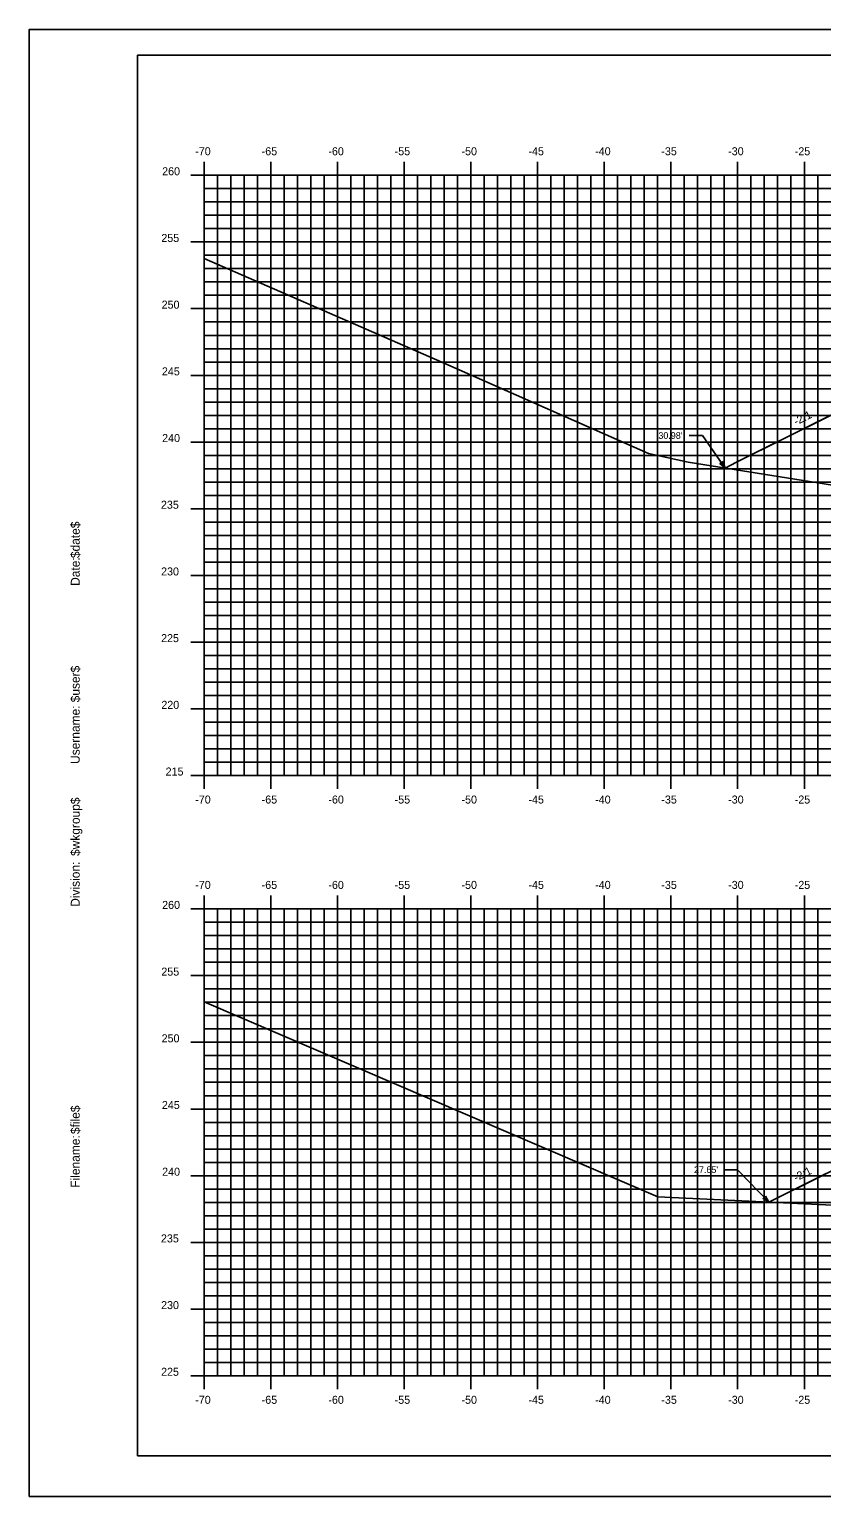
# Model space of a CAD drawing. Extents: x 1160718 to 1173142, y 616002 to 617630.
# Drawn here: x 1169657.5 to 1169716.9, y 616613.9 to 616723.9 of the extents above; entities that cross this region are included whole.
import ezdxf

# ---------------------------------------------------------------- set-up
doc = ezdxf.new("R2010")
doc.units = 0
for name, color, linetype in [('ANNOTATION', 7, 'Continuous'), ('BORDER', 7, 'Continuous'), ('D_Roadway_Centerline', 7, 'Continuous'), ('D_Roadway_SlopeLines', 7, 'Continuous'), ('H_V ANNOTATION', 7, 'Continuous'), ('MAJOR', 7, 'Continuous'), ('MINOR', 7, 'Continuous'), ('PLOT BOUNDARY', 7, 'Continuous'), ('S_Roadway_Centerline', 7, 'Continuous')]:
    doc.layers.add(name, color=color, linetype=linetype)

msp = doc.modelspace()

# ---------------------------------------------------------------- linework, layer by layer
at = {"layer": 'ANNOTATION'}
for p, q in [((1169707, 616693.42), (1169708, 616693.42)), ((1169709.7, 616690.98), (1169708, 616693.42)), ((1169709.64, 616638.38), (1169710.64, 616638.38)), ((1169712.99, 616635.94), (1169710.64, 616638.38))]:
    msp.add_line(p, q, dxfattribs=at)
for points in [[(1169709.52, 616691.46), (1169709.7, 616690.98), (1169709.31, 616691.32)], [(1169712.73, 616636.39), (1169712.99, 616635.94), (1169712.55, 616636.22)]]:
    msp.add_lwpolyline(points, close=True, dxfattribs=at)
at = {"layer": 'BORDER'}
for p, q in [((1169825.64, 616721.93), (1169665.64, 616721.93)), ((1169665.64, 616721.93), (1169665.64, 616616.93)), ((1169665.64, 616616.93), (1169825.64, 616616.93))]:
    msp.add_line(p, q, dxfattribs=at)
at = {"layer": 'D_Roadway_Centerline'}
msp.add_line((1169712.99, 616635.94), (1169717.24, 616638.07), dxfattribs=at)
msp.add_lwpolyline([(1169709.7, 616690.98), (1169710.55, 616691.41), (1169717.65, 616694.95), (1169721.64, 616696.95), (1169724.64, 616697.01), (1169740.64, 616696.37), (1169756.64, 616695.73)], dxfattribs=at)
at = {"layer": 'D_Roadway_SlopeLines'}
for points in [[(1169721.64, 616696.95), (1169710.55, 616691.41)], [(1169710.55, 616691.41), (1169709.7, 616690.98)], [(1169721.64, 616640.27), (1169712.99, 616635.94)]]:
    msp.add_lwpolyline(points, dxfattribs=at)
at = {"layer": 'MAJOR'}
for p, q in [((1169670.64, 616713.93), (1169670.64, 616712.93)), ((1169675.64, 616713.93), (1169675.64, 616712.93)), ((1169680.64, 616713.93), (1169680.64, 616712.93)), ((1169685.64, 616713.93), (1169685.64, 616712.93)), ((1169690.64, 616713.93), (1169690.64, 616712.93)), ((1169695.64, 616713.93), (1169695.64, 616712.93)), ((1169700.64, 616713.93), (1169700.64, 616712.93)), ((1169705.64, 616713.93), (1169705.64, 616712.93)), ((1169710.64, 616713.93), (1169710.64, 616712.93)), ((1169715.64, 616713.93), (1169715.64, 616712.93)), ((1169669.64, 616712.93), (1169670.64, 616712.93)), ((1169670.64, 616712.93), (1169810.64, 616712.93)), ((1169670.64, 616667.93), (1169670.64, 616712.93)), ((1169670.64, 616667.93), (1169670.64, 616712.93)), ((1169670.64, 616712.93), (1169810.64, 616712.93)), ((1169675.64, 616667.93), (1169675.64, 616712.93)), ((1169680.64, 616667.93), (1169680.64, 616712.93)), ((1169685.64, 616667.93), (1169685.64, 616712.93)), ((1169690.64, 616667.93), (1169690.64, 616712.93)), ((1169695.64, 616667.93), (1169695.64, 616712.93)), ((1169700.64, 616667.93), (1169700.64, 616712.93)), ((1169705.64, 616667.93), (1169705.64, 616712.93)), ((1169710.64, 616667.93), (1169710.64, 616712.93)), ((1169715.64, 616667.93), (1169715.64, 616712.93)), ((1169669.64, 616707.93), (1169670.64, 616707.93)), ((1169670.64, 616707.93), (1169810.64, 616707.93)), ((1169669.64, 616702.93), (1169670.64, 616702.93)), ((1169670.64, 616702.93), (1169810.64, 616702.93)), ((1169669.64, 616697.93), (1169670.64, 616697.93)), ((1169670.64, 616697.93), (1169810.64, 616697.93)), ((1169669.64, 616692.93), (1169670.64, 616692.93)), ((1169670.64, 616692.93), (1169810.64, 616692.93)), ((1169669.64, 616687.93), (1169670.64, 616687.93)), ((1169670.64, 616687.93), (1169810.64, 616687.93)), ((1169669.64, 616682.93), (1169670.64, 616682.93)), ((1169670.64, 616682.93), (1169810.64, 616682.93)), ((1169669.64, 616677.93), (1169670.64, 616677.93)), ((1169670.64, 616677.93), (1169810.64, 616677.93)), ((1169669.64, 616672.93), (1169670.64, 616672.93)), ((1169670.64, 616672.93), (1169810.64, 616672.93)), ((1169669.64, 616667.93), (1169670.64, 616667.93)), ((1169670.64, 616667.93), (1169810.64, 616667.93)), ((1169670.64, 616667.93), (1169810.64, 616667.93)), ((1169670.64, 616666.93), (1169670.64, 616667.93)), ((1169675.64, 616666.93), (1169675.64, 616667.93)), ((1169680.64, 616666.93), (1169680.64, 616667.93)), ((1169685.64, 616666.93), (1169685.64, 616667.93)), ((1169690.64, 616666.93), (1169690.64, 616667.93)), ((1169695.64, 616666.93), (1169695.64, 616667.93)), ((1169700.64, 616666.93), (1169700.64, 616667.93)), ((1169705.64, 616666.93), (1169705.64, 616667.93)), ((1169710.64, 616666.93), (1169710.64, 616667.93)), ((1169715.64, 616666.93), (1169715.64, 616667.93)), ((1169670.64, 616658.93), (1169670.64, 616657.93)), ((1169675.64, 616658.93), (1169675.64, 616657.93)), ((1169680.64, 616658.93), (1169680.64, 616657.93)), ((1169685.64, 616658.93), (1169685.64, 616657.93)), ((1169690.64, 616658.93), (1169690.64, 616657.93)), ((1169695.64, 616658.93), (1169695.64, 616657.93)), ((1169700.64, 616658.93), (1169700.64, 616657.93)), ((1169705.64, 616658.93), (1169705.64, 616657.93)), ((1169710.64, 616658.93), (1169710.64, 616657.93)), ((1169715.64, 616658.93), (1169715.64, 616657.93)), ((1169669.64, 616657.93), (1169670.64, 616657.93)), ((1169670.64, 616657.93), (1169810.64, 616657.93)), ((1169670.64, 616622.93), (1169670.64, 616657.93)), ((1169670.64, 616622.93), (1169670.64, 616657.93)), ((1169670.64, 616657.93), (1169810.64, 616657.93)), ((1169675.64, 616622.93), (1169675.64, 616657.93)), ((1169680.64, 616622.93), (1169680.64, 616657.93)), ((1169685.64, 616622.93), (1169685.64, 616657.93)), ((1169690.64, 616622.93), (1169690.64, 616657.93)), ((1169695.64, 616622.93), (1169695.64, 616657.93)), ((1169700.64, 616622.93), (1169700.64, 616657.93)), ((1169705.64, 616622.93), (1169705.64, 616657.93)), ((1169710.64, 616622.93), (1169710.64, 616657.93)), ((1169715.64, 616622.93), (1169715.64, 616657.93)), ((1169669.64, 616652.93), (1169670.64, 616652.93)), ((1169670.64, 616652.93), (1169810.64, 616652.93)), ((1169669.64, 616647.93), (1169670.64, 616647.93)), ((1169670.64, 616647.93), (1169810.64, 616647.93)), ((1169669.64, 616642.93), (1169670.64, 616642.93)), ((1169670.64, 616642.93), (1169810.64, 616642.93)), ((1169669.64, 616637.93), (1169670.64, 616637.93)), ((1169670.64, 616637.93), (1169810.64, 616637.93)), ((1169669.64, 616632.93), (1169670.64, 616632.93)), ((1169670.64, 616632.93), (1169810.64, 616632.93)), ((1169669.64, 616627.93), (1169670.64, 616627.93)), ((1169670.64, 616627.93), (1169810.64, 616627.93)), ((1169669.64, 616622.93), (1169670.64, 616622.93)), ((1169670.64, 616622.93), (1169810.64, 616622.93)), ((1169670.64, 616622.93), (1169810.64, 616622.93)), ((1169670.64, 616621.93), (1169670.64, 616622.93)), ((1169675.64, 616621.93), (1169675.64, 616622.93)), ((1169680.64, 616621.93), (1169680.64, 616622.93)), ((1169685.64, 616621.93), (1169685.64, 616622.93)), ((1169690.64, 616621.93), (1169690.64, 616622.93)), ((1169695.64, 616621.93), (1169695.64, 616622.93)), ((1169700.64, 616621.93), (1169700.64, 616622.93)), ((1169705.64, 616621.93), (1169705.64, 616622.93)), ((1169710.64, 616621.93), (1169710.64, 616622.93)), ((1169715.64, 616621.93), (1169715.64, 616622.93))]:
    msp.add_line(p, q, dxfattribs=at)
at = {"layer": 'MINOR'}
for p, q in [((1169671.64, 616667.93), (1169671.64, 616712.93)), ((1169672.64, 616667.93), (1169672.64, 616712.93)), ((1169673.64, 616667.93), (1169673.64, 616712.93)), ((1169674.64, 616667.93), (1169674.64, 616712.93)), ((1169676.64, 616667.93), (1169676.64, 616712.93)), ((1169677.64, 616667.93), (1169677.64, 616712.93)), ((1169678.64, 616667.93), (1169678.64, 616712.93)), ((1169679.64, 616667.93), (1169679.64, 616712.93)), ((1169681.64, 616667.93), (1169681.64, 616712.93)), ((1169682.64, 616667.93), (1169682.64, 616712.93)), ((1169683.64, 616667.93), (1169683.64, 616712.93)), ((1169684.64, 616667.93), (1169684.64, 616712.93)), ((1169686.64, 616667.93), (1169686.64, 616712.93)), ((1169687.64, 616667.93), (1169687.64, 616712.93)), ((1169688.64, 616667.93), (1169688.64, 616712.93)), ((1169689.64, 616667.93), (1169689.64, 616712.93)), ((1169691.64, 616667.93), (1169691.64, 616712.93)), ((1169692.64, 616667.93), (1169692.64, 616712.93)), ((1169693.64, 616667.93), (1169693.64, 616712.93)), ((1169694.64, 616667.93), (1169694.64, 616712.93)), ((1169696.64, 616667.93), (1169696.64, 616712.93)), ((1169697.64, 616667.93), (1169697.64, 616712.93)), ((1169698.64, 616667.93), (1169698.64, 616712.93)), ((1169699.64, 616667.93), (1169699.64, 616712.93)), ((1169701.64, 616667.93), (1169701.64, 616712.93)), ((1169702.64, 616667.93), (1169702.64, 616712.93)), ((1169703.64, 616667.93), (1169703.64, 616712.93)), ((1169704.64, 616667.93), (1169704.64, 616712.93)), ((1169706.64, 616667.93), (1169706.64, 616712.93)), ((1169707.64, 616667.93), (1169707.64, 616712.93)), ((1169708.64, 616667.93), (1169708.64, 616712.93)), ((1169709.64, 616667.93), (1169709.64, 616712.93)), ((1169711.64, 616667.93), (1169711.64, 616712.93)), ((1169712.64, 616667.93), (1169712.64, 616712.93)), ((1169713.64, 616667.93), (1169713.64, 616712.93)), ((1169714.64, 616667.93), (1169714.64, 616712.93)), ((1169716.64, 616667.93), (1169716.64, 616712.93)), ((1169670.64, 616711.93), (1169810.64, 616711.93)), ((1169670.64, 616711.93), (1169671.64, 616711.93)), ((1169670.64, 616710.93), (1169810.64, 616710.93)), ((1169670.64, 616710.93), (1169671.64, 616710.93)), ((1169670.64, 616709.93), (1169810.64, 616709.93)), ((1169670.64, 616709.93), (1169671.64, 616709.93)), ((1169670.64, 616708.93), (1169810.64, 616708.93)), ((1169670.64, 616708.93), (1169671.64, 616708.93)), ((1169670.64, 616706.93), (1169810.64, 616706.93)), ((1169670.64, 616706.93), (1169671.64, 616706.93)), ((1169670.64, 616705.93), (1169810.64, 616705.93)), ((1169670.64, 616705.93), (1169671.64, 616705.93)), ((1169670.64, 616704.93), (1169810.64, 616704.93)), ((1169670.64, 616704.93), (1169671.64, 616704.93)), ((1169670.64, 616703.93), (1169810.64, 616703.93)), ((1169670.64, 616703.93), (1169671.64, 616703.93)), ((1169670.64, 616701.93), (1169810.64, 616701.93)), ((1169670.64, 616701.93), (1169671.64, 616701.93)), ((1169670.64, 616700.93), (1169810.64, 616700.93)), ((1169670.64, 616700.93), (1169671.64, 616700.93)), ((1169670.64, 616699.93), (1169810.64, 616699.93)), ((1169670.64, 616699.93), (1169671.64, 616699.93)), ((1169670.64, 616698.93), (1169810.64, 616698.93)), ((1169670.64, 616698.93), (1169671.64, 616698.93)), ((1169670.64, 616696.93), (1169810.64, 616696.93)), ((1169670.64, 616696.93), (1169671.64, 616696.93)), ((1169670.64, 616695.93), (1169810.64, 616695.93)), ((1169670.64, 616695.93), (1169671.64, 616695.93)), ((1169670.64, 616694.93), (1169810.64, 616694.93)), ((1169670.64, 616694.93), (1169671.64, 616694.93)), ((1169670.64, 616693.93), (1169810.64, 616693.93)), ((1169670.64, 616693.93), (1169671.64, 616693.93)), ((1169670.64, 616691.93), (1169810.64, 616691.93)), ((1169670.64, 616691.93), (1169671.64, 616691.93)), ((1169670.64, 616690.93), (1169810.64, 616690.93)), ((1169670.64, 616690.93), (1169671.64, 616690.93)), ((1169670.64, 616689.93), (1169810.64, 616689.93)), ((1169670.64, 616689.93), (1169671.64, 616689.93)), ((1169670.64, 616688.93), (1169810.64, 616688.93)), ((1169670.64, 616688.93), (1169671.64, 616688.93)), ((1169670.64, 616686.93), (1169810.64, 616686.93)), ((1169670.64, 616686.93), (1169671.64, 616686.93)), ((1169670.64, 616685.93), (1169810.64, 616685.93)), ((1169670.64, 616685.93), (1169671.64, 616685.93)), ((1169670.64, 616684.93), (1169810.64, 616684.93)), ((1169670.64, 616684.93), (1169671.64, 616684.93)), ((1169670.64, 616683.93), (1169810.64, 616683.93)), ((1169670.64, 616683.93), (1169671.64, 616683.93)), ((1169670.64, 616681.93), (1169810.64, 616681.93)), ((1169670.64, 616681.93), (1169671.64, 616681.93)), ((1169670.64, 616680.93), (1169810.64, 616680.93)), ((1169670.64, 616680.93), (1169671.64, 616680.93)), ((1169670.64, 616679.93), (1169810.64, 616679.93)), ((1169670.64, 616679.93), (1169671.64, 616679.93)), ((1169670.64, 616678.93), (1169810.64, 616678.93)), ((1169670.64, 616678.93), (1169671.64, 616678.93)), ((1169670.64, 616676.93), (1169810.64, 616676.93)), ((1169670.64, 616676.93), (1169671.64, 616676.93)), ((1169670.64, 616675.93), (1169810.64, 616675.93)), ((1169670.64, 616675.93), (1169671.64, 616675.93)), ((1169670.64, 616674.93), (1169810.64, 616674.93)), ((1169670.64, 616674.93), (1169671.64, 616674.93)), ((1169670.64, 616673.93), (1169810.64, 616673.93)), ((1169670.64, 616673.93), (1169671.64, 616673.93)), ((1169670.64, 616671.93), (1169810.64, 616671.93)), ((1169670.64, 616671.93), (1169671.64, 616671.93)), ((1169670.64, 616670.93), (1169810.64, 616670.93)), ((1169670.64, 616670.93), (1169671.64, 616670.93)), ((1169670.64, 616669.93), (1169810.64, 616669.93)), ((1169670.64, 616669.93), (1169671.64, 616669.93)), ((1169670.64, 616668.93), (1169810.64, 616668.93)), ((1169670.64, 616668.93), (1169671.64, 616668.93)), ((1169671.64, 616622.93), (1169671.64, 616657.93)), ((1169672.64, 616622.93), (1169672.64, 616657.93)), ((1169673.64, 616622.93), (1169673.64, 616657.93)), ((1169674.64, 616622.93), (1169674.64, 616657.93)), ((1169676.64, 616622.93), (1169676.64, 616657.93)), ((1169677.64, 616622.93), (1169677.64, 616657.93)), ((1169678.64, 616622.93), (1169678.64, 616657.93)), ((1169679.64, 616622.93), (1169679.64, 616657.93)), ((1169681.64, 616622.93), (1169681.64, 616657.93)), ((1169682.64, 616622.93), (1169682.64, 616657.93)), ((1169683.64, 616622.93), (1169683.64, 616657.93)), ((1169684.64, 616622.93), (1169684.64, 616657.93)), ((1169686.64, 616622.93), (1169686.64, 616657.93)), ((1169687.64, 616622.93), (1169687.64, 616657.93)), ((1169688.64, 616622.93), (1169688.64, 616657.93)), ((1169689.64, 616622.93), (1169689.64, 616657.93)), ((1169691.64, 616622.93), (1169691.64, 616657.93)), ((1169692.64, 616622.93), (1169692.64, 616657.93)), ((1169693.64, 616622.93), (1169693.64, 616657.93)), ((1169694.64, 616622.93), (1169694.64, 616657.93)), ((1169696.64, 616622.93), (1169696.64, 616657.93)), ((1169697.64, 616622.93), (1169697.64, 616657.93)), ((1169698.64, 616622.93), (1169698.64, 616657.93)), ((1169699.64, 616622.93), (1169699.64, 616657.93)), ((1169701.64, 616622.93), (1169701.64, 616657.93)), ((1169702.64, 616622.93), (1169702.64, 616657.93)), ((1169703.64, 616622.93), (1169703.64, 616657.93)), ((1169704.64, 616622.93), (1169704.64, 616657.93)), ((1169706.64, 616622.93), (1169706.64, 616657.93)), ((1169707.64, 616622.93), (1169707.64, 616657.93)), ((1169708.64, 616622.93), (1169708.64, 616657.93)), ((1169709.64, 616622.93), (1169709.64, 616657.93)), ((1169711.64, 616622.93), (1169711.64, 616657.93)), ((1169712.64, 616622.93), (1169712.64, 616657.93)), ((1169713.64, 616622.93), (1169713.64, 616657.93)), ((1169714.64, 616622.93), (1169714.64, 616657.93)), ((1169716.64, 616622.93), (1169716.64, 616657.93)), ((1169670.64, 616656.93), (1169810.64, 616656.93)), ((1169670.64, 616656.93), (1169671.64, 616656.93)), ((1169670.64, 616655.93), (1169810.64, 616655.93)), ((1169670.64, 616655.93), (1169671.64, 616655.93)), ((1169670.64, 616654.93), (1169810.64, 616654.93)), ((1169670.64, 616654.93), (1169671.64, 616654.93)), ((1169670.64, 616653.93), (1169810.64, 616653.93)), ((1169670.64, 616653.93), (1169671.64, 616653.93)), ((1169670.64, 616651.93), (1169810.64, 616651.93)), ((1169670.64, 616651.93), (1169671.64, 616651.93)), ((1169670.64, 616650.93), (1169810.64, 616650.93)), ((1169670.64, 616650.93), (1169671.64, 616650.93)), ((1169670.64, 616649.93), (1169810.64, 616649.93)), ((1169670.64, 616649.93), (1169671.64, 616649.93)), ((1169670.64, 616648.93), (1169810.64, 616648.93)), ((1169670.64, 616648.93), (1169671.64, 616648.93)), ((1169670.64, 616646.93), (1169810.64, 616646.93)), ((1169670.64, 616646.93), (1169671.64, 616646.93)), ((1169670.64, 616645.93), (1169810.64, 616645.93)), ((1169670.64, 616645.93), (1169671.64, 616645.93)), ((1169670.64, 616644.93), (1169810.64, 616644.93)), ((1169670.64, 616644.93), (1169671.64, 616644.93)), ((1169670.64, 616643.93), (1169810.64, 616643.93)), ((1169670.64, 616643.93), (1169671.64, 616643.93)), ((1169670.64, 616641.93), (1169810.64, 616641.93)), ((1169670.64, 616641.93), (1169671.64, 616641.93)), ((1169670.64, 616640.93), (1169810.64, 616640.93)), ((1169670.64, 616640.93), (1169671.64, 616640.93)), ((1169670.64, 616639.93), (1169810.64, 616639.93)), ((1169670.64, 616639.93), (1169671.64, 616639.93)), ((1169670.64, 616638.93), (1169810.64, 616638.93)), ((1169670.64, 616638.93), (1169671.64, 616638.93)), ((1169670.64, 616636.93), (1169810.64, 616636.93)), ((1169670.64, 616636.93), (1169671.64, 616636.93)), ((1169670.64, 616635.93), (1169810.64, 616635.93)), ((1169670.64, 616635.93), (1169671.64, 616635.93)), ((1169670.64, 616634.93), (1169810.64, 616634.93)), ((1169670.64, 616634.93), (1169671.64, 616634.93)), ((1169670.64, 616633.93), (1169810.64, 616633.93)), ((1169670.64, 616633.93), (1169671.64, 616633.93)), ((1169670.64, 616631.93), (1169810.64, 616631.93)), ((1169670.64, 616631.93), (1169671.64, 616631.93)), ((1169670.64, 616630.93), (1169810.64, 616630.93)), ((1169670.64, 616630.93), (1169671.64, 616630.93)), ((1169670.64, 616629.93), (1169810.64, 616629.93)), ((1169670.64, 616629.93), (1169671.64, 616629.93)), ((1169670.64, 616628.93), (1169810.64, 616628.93)), ((1169670.64, 616628.93), (1169671.64, 616628.93)), ((1169670.64, 616626.93), (1169810.64, 616626.93)), ((1169670.64, 616626.93), (1169671.64, 616626.93)), ((1169670.64, 616625.93), (1169810.64, 616625.93)), ((1169670.64, 616625.93), (1169671.64, 616625.93)), ((1169670.64, 616624.93), (1169810.64, 616624.93)), ((1169670.64, 616624.93), (1169671.64, 616624.93)), ((1169670.64, 616623.93), (1169810.64, 616623.93)), ((1169670.64, 616623.93), (1169671.64, 616623.93))]:
    msp.add_line(p, q, dxfattribs=at)
at = {"layer": 'PLOT BOUNDARY'}
msp.add_lwpolyline([(1169657.54, 616613.87), (1169827.54, 616613.87), (1169827.54, 616723.87), (1169657.54, 616723.87)], close=True, dxfattribs=at)
at = {"layer": 'S_Roadway_Centerline'}
for points in [[(1169670.64, 616706.68), (1169688.47, 616698.91), (1169703.96, 616692.06), (1169706.94, 616691.42), (1169739.39, 616686.25), (1169754.54, 616683.08), (1169761.03, 616682.1), (1169768.7, 616677.97), (1169770.94, 616677.35), (1169780.02, 616681.43), (1169810.64, 616696.88)], [(1169670.64, 616650.97), (1169704.67, 616636.34), (1169734.53, 616634.92), (1169743.61, 616633.43), (1169759.09, 616632.79), (1169784.92, 616633.88), (1169790.65, 616634.03), (1169793.67, 616635.16), (1169810.64, 616642.12)]]:
    msp.add_lwpolyline(points, dxfattribs=at)

# ---------------------------------------------------------------- texts
at = {"layer": 'ANNOTATION'}
for p in [(1169715.02, 616694.16), (1169715.02, 616637.48)]:
    msp.add_text('-2:1', height=0.6, rotation=26.5651, dxfattribs=at).set_placement(p)
for s, p in [("30.98'", (1169704.7, 616693.17)), ("27.65'", (1169707.37, 616638.13))]:
    msp.add_text(s, height=0.5, dxfattribs=at).set_placement(p)
at = {"layer": 'BORDER'}
for s, p in [('$date$', (1169661.32, 616684.23)), ('Date:', (1169661.32, 616682.15)), ('$user$', (1169661.32, 616673.42)), ('Username:', (1169661.32, 616668.8)), ('$wkgroup$', (1169661.32, 616661.9)), ('Division:', (1169661.32, 616658.09)), ('$file$', (1169661.32, 616641.05)), ('Filename:', (1169661.32, 616637.03))]:
    msp.add_text(s, height=0.67, rotation=90, dxfattribs=at).set_placement(p)
at = {"layer": 'H_V ANNOTATION'}
for s, p in [('-70', (1169669.98, 616714.43)), ('-65', (1169674.96, 616714.43)), ('-60', (1169679.96, 616714.43)), ('-55', (1169684.93, 616714.43)), ('-50', (1169689.94, 616714.43)), ('-45', (1169694.96, 616714.43)), ('-40', (1169699.96, 616714.43)), ('-35', (1169704.92, 616714.43)), ('-30', (1169709.93, 616714.43)), ('-25', (1169714.92, 616714.43)), ('260', (1169667.5, 616712.93)), ('255', (1169667.44, 616707.93)), ('250', (1169667.46, 616702.93)), ('245', (1169667.48, 616697.93)), ('240', (1169667.5, 616692.93)), ('235', (1169667.41, 616687.93)), ('230', (1169667.42, 616682.93)), ('225', (1169667.42, 616677.93)), ('220', (1169667.44, 616672.93)), ('215', (1169667.76, 616667.93)), ('-70', (1169669.98, 616665.83)), ('-65', (1169674.96, 616665.83)), ('-60', (1169679.96, 616665.83)), ('-55', (1169684.93, 616665.83)), ('-50', (1169689.94, 616665.83)), ('-45', (1169694.96, 616665.83)), ('-40', (1169699.96, 616665.83)), ('-35', (1169704.92, 616665.83)), ('-30', (1169709.93, 616665.83)), ('-25', (1169714.92, 616665.83)), ('-70', (1169669.98, 616659.43)), ('-65', (1169674.96, 616659.43)), ('-60', (1169679.96, 616659.43)), ('-55', (1169684.93, 616659.43)), ('-50', (1169689.94, 616659.43)), ('-45', (1169694.96, 616659.43)), ('-40', (1169699.96, 616659.43)), ('-35', (1169704.92, 616659.43)), ('-30', (1169709.93, 616659.43)), ('-25', (1169714.92, 616659.43)), ('260', (1169667.5, 616657.93)), ('255', (1169667.44, 616652.93)), ('250', (1169667.46, 616647.93)), ('245', (1169667.48, 616642.93)), ('240', (1169667.5, 616637.93)), ('235', (1169667.41, 616632.93)), ('230', (1169667.42, 616627.93)), ('225', (1169667.42, 616622.93)), ('-70', (1169669.98, 616620.83)), ('-65', (1169674.96, 616620.83)), ('-60', (1169679.96, 616620.83)), ('-55', (1169684.93, 616620.83)), ('-50', (1169689.94, 616620.83)), ('-45', (1169694.96, 616620.83)), ('-40', (1169699.96, 616620.83)), ('-35', (1169704.92, 616620.83)), ('-30', (1169709.93, 616620.83)), ('-25', (1169714.92, 616620.83))]:
    msp.add_text(s, height=0.6, dxfattribs=at).set_placement(p)

doc.saveas('drawing.dxf')
